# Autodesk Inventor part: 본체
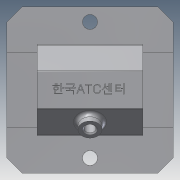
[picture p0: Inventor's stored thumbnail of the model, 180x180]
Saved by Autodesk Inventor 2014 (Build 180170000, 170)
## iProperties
Created: 2018-06
Part Number: 본체
Material: 알루미늄 6061
Document SubType Name: Modeling
Designer: sda
Mass: 553.538 g
Surface Area: 601.27 cm^2
Volume: 204.258 cm^3
Density: 2.71 g/cm^3
Appearance: 알루미늄 - 평지
Author: sda
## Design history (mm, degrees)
node "작업 평면1"
node "작업 평면2"
node "작업 평면3"
sketch "스케치2"
  geometry: L1 (12.426, 30)-(30, 12.426); L2 (30, 12.426)-(30, -12.426); L3 (30, -12.426)-(12.426, -30); L4 (12.426, -30)-(-12.426, -30); L5 (-12.426, -30)-(-30, -12.426); L6 (-30, -12.426)-(-30, 12.426); L7 (-30, 12.426)-(-12.426, 30); L8 (-12.426, 30)-(12.426, 30); 3 further points
  constraints: 16 end point, 1 horizontal, 1 midpoint, 17 other
extrude "돌출1" new body sketch "스케치2" stored distance "d4" = 70; taper "d5" = 0 deg
sketch "스케치4"
  geometry: L1 (-35, 30)-(35, 30) reference; L2 (-35, 30)-(-35, 12.426) reference; L3 (-35, 12.426)-(35, 12.426) reference; L4 (-35, 30)-(-35, 12.426) reference; L5 (-35, 30)-(35, 30) reference; L6 (35, 12.426)-(35, 30) reference; L7 (-35, -12.426)-(35, -12.426) reference; L8 (-35, 12.426)-(-35, -12.426) reference; L9 (-35, 12.426)-(35, 12.426) reference; L10 (35, -12.426)-(35, 12.426) reference; L11 (-35, -30)-(35, -30) reference; L12 (-35, -12.426)-(-35, -30) reference; L13 (-35, -12.426)-(35, -12.426) reference; L14 (35, -30)-(35, -12.426) reference; L15 (0, 25)-(20, 25); L16 (20, 25)-(20, 14); L17 (20, 14)-(23, 14); L18 (23, 14)-(23, 16); L19 (23, 16)-(35, 16); L20 (-35, 0)-(35, 0); L21 (0, 0)-(0, 30); L22 (0, 25)-(-20, 25); L23 (-20, 25)-(-20, 14); L24 (-20, 14)-(-23, 14); L25 (-23, 14)-(-23, 16); L26 (-23, 16)-(-35, 16); L27 (-35, 16)-(-35, 0); L28 (35, 16)-(35, 0)
  constraints: 28 end point, 5 symmetric about line, 3 midpoint, 2 collinear, 2 point on line, 1 perpendicular
  dimensions: "d7" = 32 diameter of L19 L20; "d8" = 50 diameter of L15 L20; "d9" = 28 diameter of L17 L20; "d10" = 12 distance of L18.end L19.end; "d11" = 3 distance of L16.end L17.end; "d13" = 11 distance of L15.end L16.end; "d14" = 32 diameter of L26 L20 (derived); "d15" = 2 distance of L24.end L25.end
revolve "회전1" sketch "스케치4" stored, may be unused: angle "d16" = 90 deg
chamfer "모따기2" distance "d20" = 1; stored, may be unused: second distance "d21" = 2, angle "d22" = 45 deg
fillet "모깎기1" dims "d23" = 0.3
fillet "모깎기2" dims "d24" = 3
node "작업 평면4"
sketch "스케치6"
  geometry: L1 (-45, 55)-(45, 55); L2 (55, 45)-(55, -45); L3 (45, -55)-(-45, -55); L4 (-55, -45)-(-55, 45); L5 (-55, 55)-(55, -55); L6 (55, 55)-(-55, -55); L7 (-45, 55)-(-55, 45); L8 (-55, -45)-(-45, -55); L9 (45, -55)-(55, -45); L10 (55, 45)-(45, 55); 3 further points
  constraints: 20 end point, 8 point on line, 4 midpoint, 2 parallel, 1 horizontal, 1 perpendicular
  dimensions: "d26" = 110 distance of L5.end L6.end; "d27" = 110 distance of L6.start L5.end; "d28" = 10 distance of L1.start L5.start; "d29" = 10 distance of L4.end L5.start (= d28); "d30" = 10 distance of L4.start L6.end (= d28); "d31" = 10 distance of L3.end L6.end (= d30); "d32" = 10 distance of L3.start L5.end (= d28); "d33" = 10 distance of L2.end L5.end (= d32); "d34" = 10 distance of L2.start L6.start (= d28); "d35" = 10 distance of L1.end L6.start (= d34)
extrude "돌출2" join sketch "스케치6" distance "d38" = 5; taper "d39" = 0 deg
sketch "스케치7"
  geometry: L1 (-45, 55)-(45, 55); L2 (55, 45)-(55, -45); L3 (45, -55)-(-45, -55); L4 (-55, -45)-(-55, 45); L5 (-55, 55)-(55, -55); L6 (55, 55)-(-55, -55); L7 (-45, 55)-(-55, 45); L8 (-55, -45)-(-45, -55); L9 (55, -45)-(45, -55); L10 (55, 45)-(45, 55); 1 further point
  constraints: 20 end point, 8 point on line, 2 midpoint, 2 parallel, 1 horizontal, 1 perpendicular
  dimensions: "d40" = 110 distance of L5.end L6.end; "d41" = 110 distance of L6.start L5.end; "d42" = 10 distance of L1.start L5.start; "d43" = 10 distance of L4.end L5.start (= d42); "d44" = 10 distance of L4.start L6.end (= d42); "d45" = 10 distance of L3.end L6.end (= d44); "d46" = 10 distance of L2.end L5.end (= d42); "d47" = 10 distance of L3.start L5.end (= d46); "d48" = 10 distance of L2.start L6.start (= d42); "d49" = 10 distance of L1.end L6.start (= d48)
extrude "돌출3" join sketch "스케치7" distance "d50" = 5; taper "d51" = 0 deg
sketch "스케치8"
  geometry: L1 (45, 55)-(-45, 55) reference; L2 (-45, -55)-(-45, 0); L3 (45, -55)-(45, 0); 1 further point
  constraints: 4 end point, 1 parallel, 1 perpendicular
sketch "스케치9"
  geometry: L1 (-25, 55)-(25, 55); L2 (25, 55)-(25, -55); L3 (25, -55)-(-25, -55); L4 (-25, -55)-(-25, 55); L5 (-25, 55)-(25, -55); L6 (25, 55)-(-25, -55); L7 (-45, -55)-(-45, 0); L8 (45, -55)-(45, 0); 3 further points
  constraints: 16 end point, 4 parallel, 2 coincident, 2 midpoint, 1 horizontal, 1 perpendicular
  dimensions: "d52" = 50 distance of L2.end L3.end; "d53" = 110 distance of L1.end L2.end
extrude "돌출4" join sketch "스케치9" distance "d54" = 5; taper "d55" = 0 deg
hole "구멍1" sketch "스케치8" diameter "d56" = 10; stored, may be unused: countersink angle "d60" = 90 deg, drill point angle "d62" = 118 deg; dims "d57" = 6, "d58" = 4, "d59" = 2, "d61" = 8
sketch "스케치10"
  geometry: L1 (5, 19)-(5, -19); L2 (-5, -19)-(-5, 19); L3 (-5, 19)-(5, -19); L4 (5, 19)-(-5, -19); A1 r 5 centre (0, 19) between (5, 19) and (-5, 19); A2 r 5 centre (0, -19) between (-5, -19) and (5, -19); 1 further point
  constraints: 8 end point, 4 point on circle, 2 centre point, 2 midpoint, 1 parallel
  dimensions: "d63" = 10 distance of L1.end L2.start; "d64" = 38 distance of L1.start L1.end
extrude "돌출5" join sketch "스케치10" stored distance "d65" = 5; taper "d66" = 0 deg
fillet "모깎기3" dims "d67" = 2
sketch "스케치11" dims "d68" = 46
  geometry: C1 r 17 at (0, 0) reference; 2 further points
  constraints: 2 vertical alignment, 1 coincident, 2 other
hole "구멍2" sketch "스케치11" at (0, 23) diameter "d69" = 3.242; stored, may be unused: countersink angle "d73" = 82 deg, drill point angle "d75" = 118 deg; dims "d70" = 8, "d71" = 3.023, "d72" = 2, "d74" = 10
node "작업 평면5"
sketch "스케치12"
  geometry: C1 r 8 at (-11.426, 35); 1 further point
  constraints: 1 centre point, 1 coincident
  dimensions: "d80" = 16 diameter of C1
extrude "돌출6" join sketch "스케치12" stored distance "d81" = 5; taper "d82" = 0 deg
sketch "스케치13"
  geometry: C1 r 8 at (0, 0) reference; C2 r 4 at (0, 0)
  constraints: 1 centre point, 1 coincident
  dimensions: "d83" = 8 diameter of C2
extrude "돌출7" cut sketch "스케치13" stored distance "d84" = 5; taper "d85" = 0 deg
fillet "모깎기4" dims "d86" = 3
chamfer "모따기3" distance "d87" = 1; stored, may be unused: second distance "d88" = 2, angle "d89" = 45 deg
node "작업 평면6"
sketch "스케치14"
  geometry: 2 further points
  constraints: 1 other
feature "엠보싱1" sketch "스케치14" dims "d91" = 0.5, "d92" = 0
fillet "모깎기5" dims "d93" = 1
node "솔리드1"
mirror "대칭1"
pattern_circular "원형 패턴1" dims angle "d77" = 360 deg
mirror "대칭2"
node "투영된 루프1"
node "투영된 루프2"
node "투영된 루프3"
other parameters: "d0" = 0, "d1" = 0, "d2" = 0, "d25" = -62, "d90" = 69
